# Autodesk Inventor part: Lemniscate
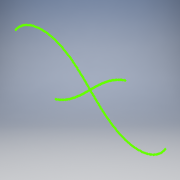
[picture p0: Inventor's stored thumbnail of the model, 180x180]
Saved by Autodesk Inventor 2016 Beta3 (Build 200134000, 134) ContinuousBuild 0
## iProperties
Created: 2008-02
Part Number: Lemniscate
Document SubType Name: Modeling
Designer: Autodesk, Inc.
Density: 1 g/cm^3
Material: Generic
Appearance: Default
Author: Autodesk, Inc.
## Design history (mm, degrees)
sketch "Sketch1"
  geometry: 299 further points
  constraints: 299 other
